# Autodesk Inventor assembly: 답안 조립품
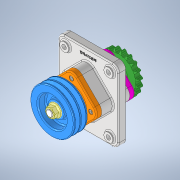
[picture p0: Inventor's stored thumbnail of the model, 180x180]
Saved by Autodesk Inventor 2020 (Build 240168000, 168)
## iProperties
Created: 2021-07
Part Number: 답안 조립품
Document SubType Name: Assembly
Designer: Owner
Author: Owner
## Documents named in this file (16)
- C:\Users\Owner\Desktop\710707V1013\710707V1013\답안 조립품.iam
- C:\Users\Owner\Desktop\710707V1013\710707V1013\본체.ipt
- C:\Users\Owner\Desktop\710707V1013\710707V1013\M16 너트.ipt
- C:\Users\Owner\Desktop\710707V1013\710707V1013\V-벨트풀리.ipt
- C:\Users\Owner\Desktop\710707V1013\710707V1013\멈춤나사 M4.ipt
- C:\Users\Owner\Desktop\710707V1013\710707V1013\베어링 6206.ipt
- C:\Users\Owner\Desktop\710707V1013\710707V1013\볼트 M6.ipt
- C:\Users\Owner\Desktop\710707V1013\710707V1013\부시.ipt
- C:\Users\Owner\Desktop\710707V1013\710707V1013\오일실 30x42x8.ipt
- C:\Users\Owner\Desktop\710707V1013\710707V1013\오일실 30x45x8.ipt
- C:\Users\Owner\Desktop\710707V1013\710707V1013\체인 스프로킷.ipt
- C:\Users\Owner\Desktop\710707V1013\710707V1013\축.ipt
- C:\Users\Owner\Desktop\710707V1013\710707V1013\커버A.ipt
- C:\Users\Owner\Desktop\710707V1013\710707V1013\커버B.ipt
- C:\Users\Owner\Desktop\710707V1013\710707V1013\키 6x6x18.ipt
- C:\Users\Owner\Desktop\710707V1013\710707V1013\키 6x6x20.ipt
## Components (3 placed, 2 different names)
1. M16 너트:1 — 각도:3
2. V-벨트풀리:1 — 각도:2
3. M16 너트:2
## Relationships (2: Angle 2)
- 각도:2 [Angle]: V-벨트풀리:1
- 각도:3 [Angle]: M16 너트:1
